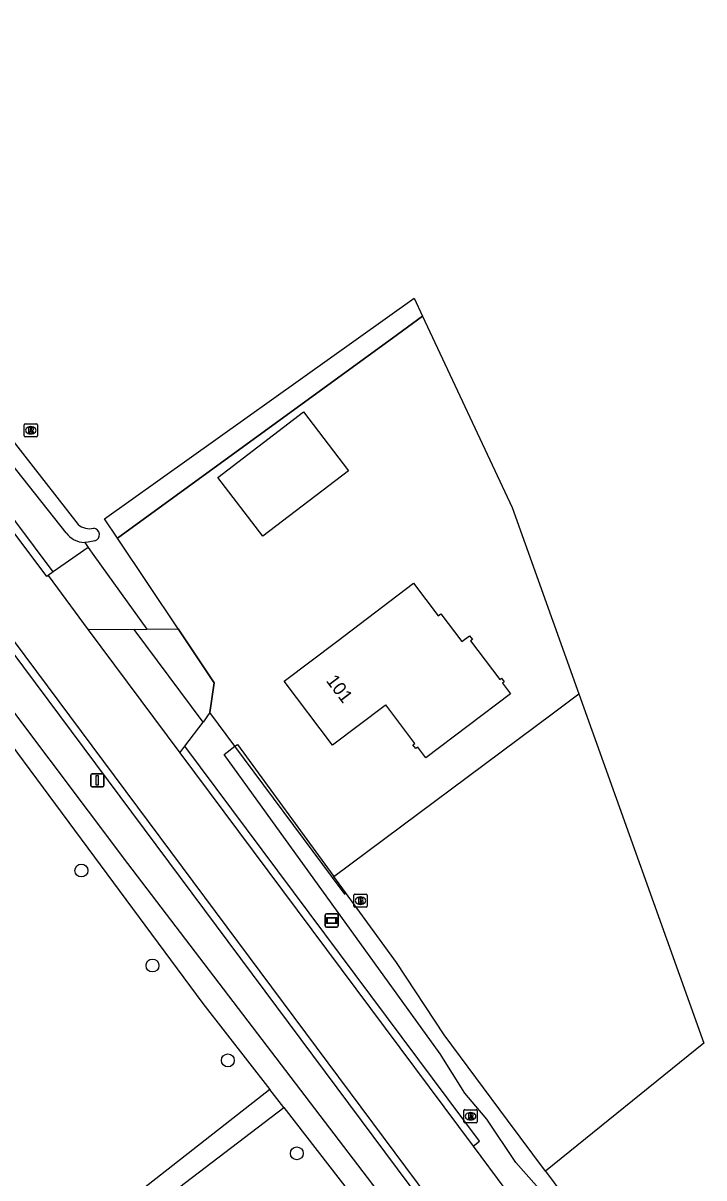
# Model space of a CAD drawing. Extents: x 164494 to 166241, y 382475 to 384494.
# Drawn here: x 164915.4 to 164967.1, y 383305.2 to 383393 of the extents above; entities that cross this region are included whole.
import ezdxf

# ---------------------------------------------------------------- set-up
doc = ezdxf.new("R2010")
doc.units = 0
for name, color, linetype in [('IMGEO_Berm_halfverhard', 7, 'Continuous'), ('IMGEO_Boom', 7, 'Continuous'), ('IMGEO_Bouwland', 7, 'Continuous'), ('IMGEO_Brandkraan', 7, 'Continuous'), ('IMGEO_Grasland_overig', 7, 'Continuous'), ('IMGEO_Groenvoorziening', 7, 'Continuous'), ('IMGEO_Hek', 7, 'Continuous'), ('IMGEO_Loofbos', 7, 'Continuous'), ('IMGEO_Pand', 7, 'Continuous'), ('IMGEO_Pand_nummerreeks', 7, 'Continuous'), ('IMGEO_Parkeervlak_open', 7, 'Continuous'), ('IMGEO_Rijbaan_lokaal_gesloten', 7, 'Continuous'), ('IMGEO_Rioolput', 7, 'Continuous'), ('IMGEO_Verkeersbordpaal', 7, 'Continuous'), ('IMGEO_Verklikker', 7, 'Continuous'), ('IMGEO_Voetpad_open', 7, 'Continuous'), ('IMGEO_Waterloop', 7, 'Continuous')]:
    doc.layers.add(name, color=color, linetype=linetype)

msp = doc.modelspace()

# ---------------------------------------------------------------- linework, layer by layer
at = {"layer": 'IMGEO_Berm_halfverhard'}
for points in [[(164917.658, 383351.268), (164910.612, 383360.672), (164905.471, 383367.54), (164899.498, 383375.583), (164890.317, 383388.044), (164882.908, 383398.057), (164874.244, 383409.65), (164866.601, 383420.14), (164858.738, 383431.203), (164853.899, 383438.366), (164849.084, 383445.806), (164847.079, 383449.156), (164846.701, 383448.936)], [(164898.891, 383366.181), (164946.531, 383302.21), (164947.016, 383302.564)], [(164949.568, 383307.631), (164950.049, 383307.989), (164927.659, 383338.025)]]:
    msp.add_lwpolyline(points, dxfattribs=at)
at = {"layer": 'IMGEO_Boom'}
for centre in [(164919.798, 383328.573), (164925.199, 383321.351), (164930.926, 383314.139), (164936.164, 383307.074)]:
    msp.add_circle(centre, 0.489, dxfattribs=at)
at = {"layer": 'IMGEO_Bouwland'}
for points in [[(164945.721, 383370.725), (164952.534, 383356.179), (164957.606, 383341.995)], [(164927.15, 383346.95), (164922.544, 383353.832)]]:
    msp.add_lwpolyline(points, dxfattribs=at)
at = {"layer": 'IMGEO_Brandkraan'}
for p, q in [((164940.502, 383325.856), (164940.502, 383326.708)), ((164940.577, 383326.782), (164941.429, 383326.782)), ((164941.013, 383326.002), (164940.988, 383326.002)), ((164940.99, 383326.562), (164941.015, 383326.562)), ((164941.503, 383326.708), (164941.503, 383325.856)), ((164941.429, 383325.782), (164940.577, 383325.782))]:
    msp.add_line(p, q, dxfattribs=at)
for points in [[(164940.502, 383325.856), (164940.502, 383326.708)], [(164940.577, 383326.782), (164941.429, 383326.782)], [(164940.85, 383326.482), (164940.85, 383326.082), (164941.063, 383326.082)], [(164941.081, 383326.482), (164940.85, 383326.482)], [(164941.029, 383326.401), (164940.975, 383326.401), (164940.975, 383326.325)], [(164940.975, 383326.325), (164941.028, 383326.325)], [(164941.037, 383326.249), (164940.975, 383326.249), (164940.975, 383326.168)], [(164940.975, 383326.168), (164941.037, 383326.168)], [(164941.503, 383326.708), (164941.503, 383325.856)], [(164941.429, 383325.782), (164940.577, 383325.782)]]:
    msp.add_lwpolyline(points, dxfattribs=at)
for centre, radius, start, end in [((164940.579, 383326.706), 0.0765, 91.55205, 178.44795), ((164940.579, 383326.706), 0.0765, 91.55205, 178.44795), ((164941.03, 383326.363), 0.0379, 267.82845, 90.93552), ((164941.038, 383326.208), 0.0404, 269.87594, 90.50774), ((164941.069, 383326.333), 0.251, 268.66757, 293.53466), ((164941.085, 383326.337), 0.145, 59.4692, 91.53667), ((164941.11, 383326.384), 0.0922, 285.51372, 58.15012), ((164941.115, 383326.192), 0.105, 301.31148, 78.98903), ((164941.427, 383326.706), 0.0765, 1.55205, 88.44795), ((164941.427, 383326.706), 0.0765, 1.55205, 88.44795), ((164940.579, 383325.858), 0.0765, 181.55205, 268.44795), ((164940.579, 383325.858), 0.0765, 181.55205, 268.44795), ((164941.427, 383325.858), 0.0765, 271.55205, 358.44795), ((164941.427, 383325.858), 0.0765, 271.55205, 358.44795)]:
    msp.add_arc(centre, radius, start, end, dxfattribs=at)
for centre, major_axis, ratio, start_param, end_param in [((164940.989, 383326.282), (-0.387, 0.002), 0.722429, 4.712389, 7.853982), ((164941.014, 383326.282), (-0.39, 0.002), 0.717154, 1.570796, 4.712389)]:
    msp.add_ellipse(centre, major_axis=major_axis, ratio=ratio, start_param=start_param, end_param=end_param, dxfattribs=at)
at = {"layer": 'IMGEO_Grasland_overig'}
for points in [[(164922.544, 383353.832), (164921.547, 383355.321), (164945.08, 383372.094), (164945.721, 383370.725)], [(164945.721, 383370.725), (164943.812, 383369.334), (164922.544, 383353.832)], [(164920.048, 383353.519), (164920.321, 383353.128)]]:
    msp.add_lwpolyline(points, dxfattribs=at)
at = {"layer": 'IMGEO_Groenvoorziening'}
msp.add_lwpolyline([(164931.465, 383338.015), (164929.545, 383340.596)], dxfattribs=at)
at = {"layer": 'IMGEO_Hek'}
for points in [[(164943.812, 383369.334), (164945.721, 383370.725)], [(164922.544, 383353.832), (164943.812, 383369.334)], [(164927.15, 383346.95), (164922.544, 383353.832)], [(164929.545, 383340.596), (164929.893, 383342.853), (164927.15, 383346.95)], [(164931.465, 383338.015), (164929.545, 383340.596)], [(164938.876, 383328.05), (164931.465, 383338.015)], [(164939.841, 383326.753), (164938.876, 383328.05)]]:
    msp.add_lwpolyline(points, dxfattribs=at)
at = {"layer": 'IMGEO_Loofbos'}
for points in [[(164938.976, 383328.124), (164955.575, 383340.483), (164957.606, 383341.995)], [(164957.606, 383341.995), (164967.101, 383315.443), (164955.054, 383305.726)]]:
    msp.add_lwpolyline(points, dxfattribs=at)
at = {"layer": 'IMGEO_Pand'}
for points in [[(164933.586, 383353.98), (164930.165, 383358.458), (164936.684, 383363.438), (164940.105, 383358.961), (164933.586, 383353.98)], [(164945.044, 383350.408), (164946.916, 383347.935), (164947.109, 383348.081), (164948.704, 383345.973), (164949.297, 383346.422), (164949.515, 383346.135), (164949.371, 383346.027), (164951.584, 383343.103), (164951.716, 383343.202), (164951.93, 383342.919), (164951.798, 383342.82), (164952.408, 383342.014), (164945.967, 383337.14), (164945.352, 383337.954), (164945.208, 383337.845), (164944.991, 383338.132), (164945.134, 383338.241), (164942.922, 383341.164), (164942.872, 383341.126), (164938.884, 383338.108), (164935.209, 383342.965), (164939.196, 383345.983), (164945.044, 383350.408)]]:
    msp.add_lwpolyline(points, dxfattribs=at)
at = {"layer": 'IMGEO_Parkeervlak_open'}
for points in [[(164920.321, 383353.128), (164917.658, 383351.268)], [(164920.321, 383353.128), (164920.745, 383352.521), (164924.765, 383346.92)], [(164917.658, 383351.268), (164917.265, 383350.994)]]:
    msp.add_lwpolyline(points, dxfattribs=at)
at = {"layer": 'IMGEO_Rijbaan_lokaal_gesloten'}
for points in [[(164917.265, 383350.994), (164917.166, 383350.925), (164910.131, 383360.313), (164904.989, 383367.182), (164899.015, 383375.227), (164889.835, 383387.688), (164882.427, 383397.698), (164873.759, 383409.297), (164866.112, 383419.793), (164858.241, 383430.867), (164853.395, 383438.04), (164848.569, 383445.498), (164846.561, 383448.854), (164846.701, 383448.936)], [(164867.994, 383408.673), (164897.533, 383369.007), (164899.311, 383366.621), (164947.016, 383302.564)], [(164917.265, 383350.994), (164920.32, 383346.864)], [(164920.32, 383346.864), (164927.281, 383337.528)], [(164927.281, 383337.528), (164949.568, 383307.631)], [(164949.568, 383307.631), (164951.985, 383304.388)]]:
    msp.add_lwpolyline(points, dxfattribs=at)
at = {"layer": 'IMGEO_Rioolput'}
for p, q in [((164915.452, 383361.614), (164915.452, 383362.466)), ((164915.527, 383362.54), (164916.379, 383362.54)), ((164915.94, 383362.32), (164915.965, 383362.32)), ((164916.453, 383362.466), (164916.453, 383361.614)), ((164916.379, 383361.54), (164915.527, 383361.54)), ((164915.963, 383361.76), (164915.938, 383361.76)), ((164948.87, 383309.468), (164948.87, 383310.32)), ((164948.945, 383310.394), (164949.797, 383310.394)), ((164949.358, 383310.174), (164949.383, 383310.174)), ((164949.871, 383310.32), (164949.871, 383309.468)), ((164949.797, 383309.394), (164948.945, 383309.394)), ((164949.381, 383309.614), (164949.356, 383309.614))]:
    msp.add_line(p, q, dxfattribs=at)
for points in [[(164915.452, 383361.614), (164915.452, 383362.466)], [(164915.527, 383362.54), (164916.379, 383362.54)], [(164916.041, 383362.238), (164915.789, 383362.24), (164915.789, 383361.84)], [(164915.789, 383361.84), (164915.913, 383361.84), (164915.913, 383362.002), (164915.924, 383362.002)], [(164915.967, 383362.159), (164915.913, 383362.159), (164915.913, 383362.078)], [(164915.913, 383362.078), (164915.965, 383362.078)], [(164915.971, 383361.973), (164916.042, 383361.84), (164916.182, 383361.84), (164916.117, 383361.966)], [(164916.453, 383362.466), (164916.453, 383361.614)], [(164916.379, 383361.54), (164915.527, 383361.54)], [(164948.87, 383309.468), (164948.87, 383310.32)], [(164948.945, 383310.394), (164949.797, 383310.394)], [(164949.871, 383310.32), (164949.871, 383309.468)], [(164949.797, 383309.394), (164948.945, 383309.394)], [(164949.459, 383310.092), (164949.207, 383310.094), (164949.207, 383309.694)], [(164949.207, 383309.694), (164949.331, 383309.694), (164949.331, 383309.856), (164949.342, 383309.856)], [(164949.385, 383310.013), (164949.331, 383310.013), (164949.331, 383309.932)], [(164949.331, 383309.932), (164949.383, 383309.932)], [(164949.389, 383309.827), (164949.46, 383309.694), (164949.6, 383309.694), (164949.535, 383309.82)]]:
    msp.add_lwpolyline(points, dxfattribs=at)
for centre, radius, start, end in [((164915.529, 383362.464), 0.0765, 91.55205, 178.44795), ((164915.529, 383362.464), 0.0765, 91.55205, 178.44795), ((164915.923, 383361.949), 0.0533, 26.02933, 88.69889), ((164915.949, 383362.267), 0.19, 274.7715, 282.96867), ((164915.973, 383362.063), 0.0964, 77.00612, 93.18647), ((164915.987, 383362.12), 0.0378, 276.66336, 79.67722), ((164916.04, 383362.128), 0.109, 350.36119, 89.41601), ((164916.038, 383362.128), 0.112, 277.58423, 350.98172), ((164916.022, 383361.913), 0.108, 29.51342, 73.79051), ((164916.377, 383362.464), 0.0765, 1.55205, 88.44795), ((164916.377, 383362.464), 0.0765, 1.55205, 88.44795), ((164915.529, 383361.616), 0.0765, 181.55205, 268.44795), ((164915.529, 383361.616), 0.0765, 181.55205, 268.44795), ((164916.377, 383361.616), 0.0765, 271.55205, 358.44795), ((164916.377, 383361.616), 0.0765, 271.55205, 358.44795), ((164948.947, 383310.318), 0.0765, 91.55205, 178.44795), ((164948.947, 383310.318), 0.0765, 91.55205, 178.44795), ((164949.795, 383310.318), 0.0765, 1.55205, 88.44795), ((164949.795, 383310.318), 0.0765, 1.55205, 88.44795), ((164948.947, 383309.47), 0.0765, 181.55205, 268.44795), ((164948.947, 383309.47), 0.0765, 181.55205, 268.44795), ((164949.341, 383309.803), 0.0533, 26.02933, 88.69889), ((164949.367, 383310.121), 0.19, 274.7715, 282.96867), ((164949.391, 383309.917), 0.0964, 77.00612, 93.18647), ((164949.405, 383309.974), 0.0378, 276.66336, 79.67722), ((164949.458, 383309.982), 0.109, 350.36119, 89.41601), ((164949.456, 383309.982), 0.112, 277.58423, 350.98172), ((164949.44, 383309.767), 0.108, 29.51342, 73.79051), ((164949.795, 383309.47), 0.0765, 271.55205, 358.44795), ((164949.795, 383309.47), 0.0765, 271.55205, 358.44795)]:
    msp.add_arc(centre, radius, start, end, dxfattribs=at)
for centre, major_axis, ratio, start_param, end_param in [((164915.939, 383362.04), (-0.387, 0.002), 0.722429, 4.712389, 7.853982), ((164915.964, 383362.04), (-0.39, 0.002), 0.717154, 1.570796, 4.712389), ((164949.357, 383309.894), (-0.387, 0.002), 0.722429, 4.712389, 7.853982), ((164949.382, 383309.894), (-0.39, 0.002), 0.717154, 1.570796, 4.712389)]:
    msp.add_ellipse(centre, major_axis=major_axis, ratio=ratio, start_param=start_param, end_param=end_param, dxfattribs=at)
at = {"layer": 'IMGEO_Verkeersbordpaal'}
for p, q in [((164920.51, 383335.032), (164920.51, 383335.832)), ((164920.51, 383335.832), (164920.51, 383335.032)), ((164920.61, 383335.932), (164921.4, 383335.932)), ((164921.4, 383335.932), (164920.61, 383335.932)), ((164921.5, 383335.832), (164921.5, 383335.032)), ((164921.5, 383335.032), (164921.5, 383335.832)), ((164921.4, 383334.932), (164920.61, 383334.932)), ((164920.61, 383334.932), (164921.4, 383334.932))]:
    msp.add_line(p, q, dxfattribs=at)
msp.add_lwpolyline([(164920.93, 383335.807), (164921.08, 383335.807), (164921.08, 383335.057), (164920.93, 383335.057), (164920.93, 383335.807)], dxfattribs=at)
for centre, start, end in [((164920.61, 383335.832), 90, 180), ((164920.61, 383335.832), 90, 180), ((164921.4, 383335.832), 0, 90), ((164921.4, 383335.832), 360, 90), ((164920.61, 383335.032), 180, 270), ((164920.61, 383335.032), 180, 270), ((164921.4, 383335.032), 270, 0), ((164921.4, 383335.032), 270, 0)]:
    msp.add_arc(centre, 0.1, start, end, dxfattribs=at)
at = {"layer": 'IMGEO_Verklikker'}
for p, q in [((164938.317, 383324.375), (164938.317, 383325.175)), ((164938.317, 383325.175), (164938.317, 383324.375)), ((164938.417, 383325.275), (164939.207, 383325.275)), ((164939.207, 383325.275), (164938.417, 383325.275)), ((164939.307, 383325.175), (164939.307, 383324.375)), ((164939.307, 383324.375), (164939.307, 383325.175)), ((164939.207, 383324.275), (164938.417, 383324.275)), ((164938.417, 383324.275), (164939.207, 383324.275))]:
    msp.add_line(p, q, dxfattribs=at)
for points in [[(164938.418, 383325.007), (164939.206, 383325.007), (164939.206, 383324.543), (164938.418, 383324.543), (164938.418, 383325.007)], [(164938.483, 383324.942), (164938.483, 383324.608), (164939.141, 383324.608), (164939.141, 383324.942), (164938.483, 383324.942)]]:
    msp.add_lwpolyline(points, dxfattribs=at)
for centre, start, end in [((164938.417, 383325.175), 90, 180), ((164938.417, 383325.175), 90, 180), ((164939.207, 383325.175), 0, 90), ((164939.207, 383325.175), 360, 90), ((164938.417, 383324.375), 180, 270), ((164938.417, 383324.375), 180, 270), ((164939.207, 383324.375), 270, 0), ((164939.207, 383324.375), 270, 0)]:
    msp.add_arc(centre, 0.1, start, end, dxfattribs=at)
at = {"layer": 'IMGEO_Voetpad_open'}
for points in [[(164923.81, 383346.908), (164920.32, 383346.864)], [(164923.81, 383346.908), (164924.765, 383346.92)], [(164929.058, 383339.863), (164923.81, 383346.908)], [(164924.765, 383346.92), (164927.15, 383346.95)], [(164927.15, 383346.95), (164929.893, 383342.853), (164929.545, 383340.596)], [(164929.545, 383340.596), (164929.058, 383339.863)], [(164927.659, 383338.025), (164929.058, 383339.863)], [(164927.281, 383337.528), (164927.659, 383338.025)]]:
    msp.add_lwpolyline(points, dxfattribs=at)
at = {"layer": 'IMGEO_Waterloop'}
for points in [[(164896.813, 383364.002), (164902.872, 383356.577), (164911.399, 383344.917), (164923.309, 383329.117), (164956.871, 383285.126), (164961.245, 383279.38)], [(164912.922, 383363.364), (164915.309, 383360.31), (164919.551, 383354.884)], [(164918.64, 383354.243), (164911.986, 383362.627)], [(164897.462, 383360.393), (164901.768, 383355.265), (164929.019, 383318.473), (164934.105, 383311.921)], [(164920.808, 383353.647), (164920.309, 383353.536), (164920.048, 383353.519)], [(164965.877, 383288.405), (164963.265, 383291.951), (164961.672, 383294.774), (164957.743, 383299.844), (164954.375, 383304.592), (164952.798, 383306.376), (164950.606, 383309.661), (164948.931, 383311.645), (164947.057, 383314.629), (164930.651, 383337.387), (164931.465, 383338.015)], [(164931.465, 383338.015), (164931.657, 383338.164), (164938.976, 383328.124)], [(164955.054, 383305.726), (164952.187, 383309.591), (164947.361, 383316.088), (164943.74, 383321.588), (164938.976, 383328.124)], [(164934.105, 383311.921), (164874.996, 383265.615), (164875.468, 383265.013), (164935.169, 383310.551)], [(164935.169, 383310.551), (164934.105, 383311.921)], [(164935.169, 383310.551), (164955.63, 383284.19), (164960.037, 383278.075)], [(164955.054, 383305.726), (164967.059, 383289.542), (164967.017, 383288.822)]]:
    msp.add_lwpolyline(points, dxfattribs=at)
for centre, radius, start, end in [((164920.067, 383355.288), 1.769, 216.20011, 269.37503), ((164920.447, 383355.965), 1.404, 230.36947, 281.60382), ((164920.696, 383354.112), 0.479, 283.57797, 85.99959)]:
    msp.add_arc(centre, radius, start, end, dxfattribs=at)

# ---------------------------------------------------------------- texts
at = {"layer": 'IMGEO_Pand_nummerreeks'}
msp.add_text('101', height=1, rotation=307.11027, dxfattribs=at).set_placement((164938.348, 383342.993))

doc.saveas('drawing.dxf')
